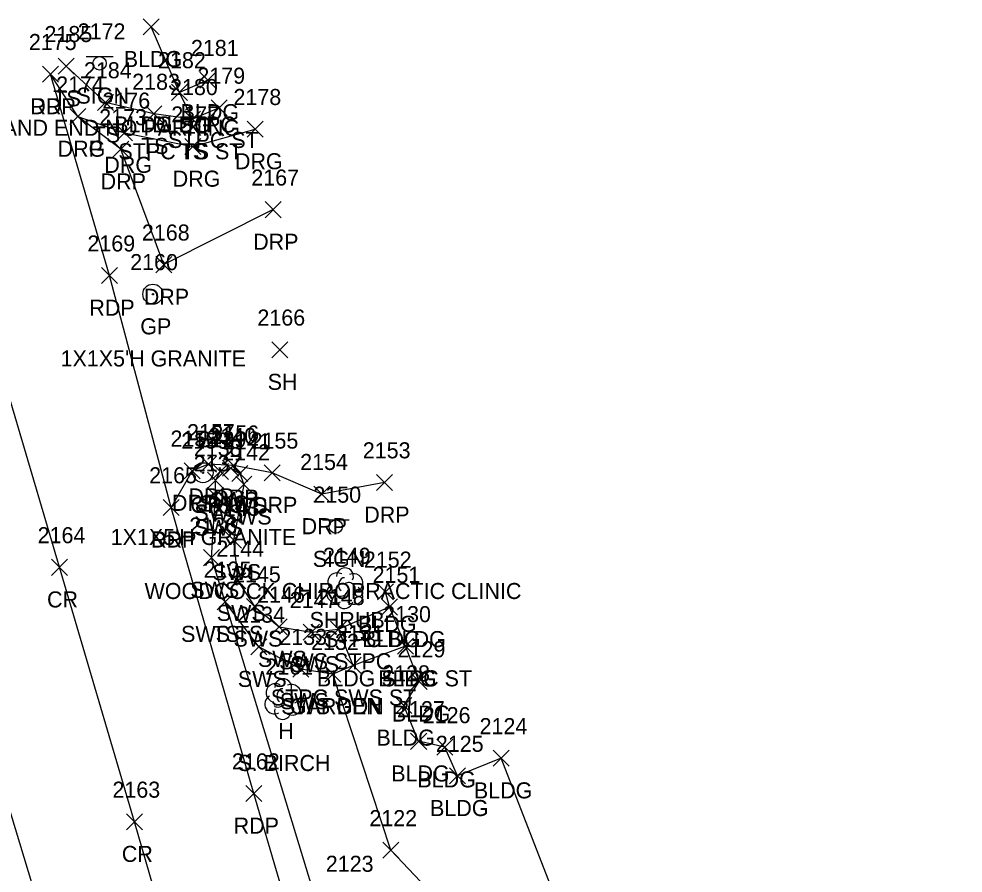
# Model space of a CAD drawing. Extents: x 1620157 to 1620595, y 115111 to 117885.
# Drawn here: x 1620218.6 to 1620336.2, y 115746 to 115852.3 of the extents above; entities that cross this region are included whole.
import ezdxf

# ---------------------------------------------------------------- set-up
doc = ezdxf.new("R2010")
doc.units = 0
for name, color, linetype in [('L_A', 7, 'Continuous'), ('L_C', 7, 'Continuous'), ('L_I', 7, 'Continuous'), ('L_TIC', 7, 'Continuous'), ('LAPB', 7, 'Continuous'), ('LBC', 7, 'Continuous'), ('LBF', 7, 'Continuous'), ('LELB', 7, 'Continuous'), ('LSH', 7, 'Continuous'), ('LTD', 7, 'Continuous'), ('P_A', 7, 'Continuous'), ('P_I', 7, 'Continuous'), ('P_TIC', 7, 'Continuous'), ('PET', 7, 'Continuous'), ('PRC', 7, 'Continuous'), ('R_A', 7, 'Continuous'), ('R_C', 7, 'Continuous'), ('R_I', 7, 'Continuous'), ('R_TIC', 7, 'Continuous'), ('RDG', 7, 'Continuous'), ('RDP', 7, 'Continuous'), ('RGP', 7, 'Continuous'), ('RSW', 7, 'Continuous'), ('S_A', 7, 'Continuous'), ('S_C', 7, 'Continuous'), ('S_I', 7, 'Continuous'), ('SSGN', 7, 'Continuous')]:
    doc.layers.add(name, color=color, linetype=linetype)

msp = doc.modelspace()

# ---------------------------------------------------------------- linework, layer by layer
at = {"layer": 'L_TIC'}
for points in [[(1620234.05, 115850.34), (1620236.05, 115852.34)], [(1620236.05, 115850.34), (1620234.05, 115852.34)], [(1620223.46, 115845.45), (1620225.46, 115847.45)], [(1620225.46, 115845.45), (1620223.46, 115847.45)], [(1620241.14, 115843.72), (1620243.14, 115845.72)], [(1620243.14, 115843.72), (1620241.14, 115845.72)], [(1620237.61, 115842.19), (1620239.61, 115844.19)], [(1620239.61, 115842.19), (1620237.61, 115844.19)], [(1620237.61, 115842.19), (1620239.61, 115844.19)], [(1620239.61, 115842.19), (1620237.61, 115844.19)], [(1620228.39, 115840.94), (1620230.39, 115842.94)], [(1620230.39, 115840.94), (1620228.39, 115842.94)], [(1620234.39, 115839.51), (1620236.39, 115841.51)], [(1620236.39, 115839.51), (1620234.39, 115841.51)], [(1620242.53, 115840.26), (1620244.53, 115842.26)], [(1620244.53, 115840.26), (1620242.53, 115842.26)], [(1620239.2, 115838.85), (1620241.2, 115840.85)], [(1620241.2, 115838.85), (1620239.2, 115840.85)], [(1620239.2, 115838.85), (1620241.2, 115840.85)], [(1620241.2, 115838.85), (1620239.2, 115840.85)], [(1620250.09, 115810.14), (1620252.09, 115812.14)], [(1620252.09, 115810.14), (1620250.09, 115812.14)], [(1620263.25, 115780), (1620265.25, 115782)], [(1620265.25, 115780), (1620263.25, 115782)], [(1620243.29, 115778.75), (1620245.29, 115780.75)], [(1620245.29, 115778.75), (1620243.29, 115780.75)], [(1620263.77, 115778.1), (1620265.77, 115780.1)], [(1620265.77, 115778.1), (1620263.77, 115780.1)], [(1620263.77, 115778.1), (1620265.77, 115780.1)], [(1620265.77, 115778.1), (1620263.77, 115780.1)], [(1620257.41, 115775.34), (1620259.41, 115777.34)], [(1620259.41, 115775.34), (1620257.41, 115777.34)], [(1620265.75, 115773.21), (1620267.75, 115775.21)], [(1620267.75, 115773.21), (1620265.75, 115775.21)], [(1620265.75, 115773.21), (1620267.75, 115775.21)], [(1620267.75, 115773.21), (1620265.75, 115775.21)], [(1620259.23, 115770.83), (1620261.23, 115772.83)], [(1620261.23, 115770.83), (1620259.23, 115772.83)], [(1620256.68, 115769.75), (1620258.68, 115771.75)], [(1620258.68, 115769.75), (1620256.68, 115771.75)], [(1620267.47, 115768.83), (1620269.47, 115770.83)], [(1620269.47, 115768.83), (1620267.47, 115770.83)], [(1620265.54, 115765.83), (1620267.54, 115767.83)], [(1620267.54, 115765.83), (1620265.54, 115767.83)], [(1620267.39, 115761.37), (1620269.39, 115763.37)], [(1620269.39, 115761.37), (1620267.39, 115763.37)], [(1620270.64, 115760.63), (1620272.64, 115762.63)], [(1620272.64, 115760.63), (1620270.64, 115762.63)], [(1620277.68, 115759.26), (1620279.68, 115761.26)], [(1620279.68, 115759.26), (1620277.68, 115761.26)], [(1620272.22, 115757.06), (1620274.22, 115759.06)], [(1620274.22, 115757.06), (1620272.22, 115759.06)], [(1620263.94, 115747.8), (1620265.94, 115749.8)], [(1620265.94, 115747.8), (1620263.94, 115749.8)]]:
    msp.add_lwpolyline(points, dxfattribs=at)
at = {"layer": 'LAPB'}
msp.add_lwpolyline([(1620278.22, 115734.77), (1620264.94, 115748.8), (1620257.68, 115770.75)], dxfattribs=at)
at = {"layer": 'LBC'}
for points in [[(1620242.14, 115844.72), (1620238.61, 115843.19), (1620235.05, 115851.34)], [(1620286.48, 115740.19), (1620278.68, 115760.26), (1620273.22, 115758.06), (1620271.64, 115761.63), (1620268.39, 115762.37), (1620266.54, 115766.83), (1620268.47, 115769.83), (1620266.75, 115774.21), (1620264.77, 115779.1), (1620264.25, 115781)]]:
    msp.add_lwpolyline(points, dxfattribs=at)
at = {"layer": 'LBF'}
for points in [[(1620243.53, 115841.26), (1620240.2, 115839.85), (1620238.61, 115843.19)], [(1620266.75, 115774.21), (1620260.23, 115771.83), (1620258.41, 115776.34), (1620264.77, 115779.1)]]:
    msp.add_lwpolyline(points, dxfattribs=at)
at = {"layer": 'LELB'}
for points in [[(1620240.2, 115839.85), (1620235.39, 115840.51), (1620229.39, 115841.94), (1620224.46, 115846.45)], [(1620266.61, 115701.28), (1620260.83, 115725.5), (1620244.29, 115779.75)]]:
    msp.add_lwpolyline(points, dxfattribs=at)
at = {"layer": 'LSH'}
msp.add_line((1620259.17, 115781.48), (1620259.17, 115781.48), dxfattribs=at)
msp.add_line((1620259.17, 115781.48), (1620259.17, 115781.48), dxfattribs=at)
msp.add_arc((1620259.21, 115782.91), 1.05, 335.5272, 180.9563, dxfattribs=at)
for centre, major_axis, ratio, start_param, end_param in [((1620258.37, 115782.15), (1.21, -0.51), 0.895232, 1.570796, 4.712389), ((1620258.96, 115781.94), (-0.208, -0.792), 0.645439, 3.141593, 6.283185), ((1620260.21, 115782.06), (-1.14, -0.48), 0.949671, 1.570796, 4.712389), ((1620258.08, 115780.77), (0.58, -1.04), 0.959034, 3.141593, 6.283185), ((1620259.67, 115781.31), (-0.5, 0.667), 0.989748, 3.141593, 6.283185), ((1620260.17, 115780.65), (-1.09, 0.79), 0.841452, 1.570796, 4.712389), ((1620259.17, 115779.98), (0.26, 1.06), 0.942809, 1.570796, 4.712389), ((1620258.71, 115780.73), (-0.625, -0.083), 0.423636, 0, 3.141593)]:
    msp.add_ellipse(centre, major_axis=major_axis, ratio=ratio, start_param=start_param, end_param=end_param, dxfattribs=at)
at = {"layer": 'LTD'}
msp.add_line((1620251.46, 115767.67), (1620251.46, 115767.67), dxfattribs=at)
msp.add_line((1620251.46, 115767.67), (1620251.46, 115767.67), dxfattribs=at)
msp.add_arc((1620251.51, 115769.11), 1.05, 335.5272, 180.9563, dxfattribs=at)
for centre, major_axis, ratio, start_param, end_param in [((1620250.67, 115768.34), (1.21, -0.51), 0.895232, 1.570796, 4.712389), ((1620252.51, 115768.26), (-1.14, -0.48), 0.949671, 1.570796, 4.712389), ((1620251.26, 115768.13), (-0.208, -0.792), 0.645439, 3.141593, 6.283185), ((1620251.96, 115767.51), (-0.5, 0.667), 0.989748, 3.141593, 6.283185), ((1620250.38, 115766.97), (0.58, -1.04), 0.959034, 3.141593, 6.283185), ((1620252.46, 115766.84), (-1.09, 0.79), 0.841452, 1.570796, 4.712389), ((1620251.46, 115766.17), (0.26, 1.06), 0.942809, 1.570796, 4.712389), ((1620251.01, 115766.92), (-0.625, -0.083), 0.423636, 0, 3.141593)]:
    msp.add_ellipse(centre, major_axis=major_axis, ratio=ratio, start_param=start_param, end_param=end_param, dxfattribs=at)
at = {"layer": 'P_TIC'}
for points in [[(1620221.52, 115844.46), (1620223.52, 115846.46)], [(1620223.52, 115844.46), (1620221.52, 115846.46)], [(1620228.87, 115819.37), (1620230.87, 115821.37)], [(1620230.87, 115819.37), (1620228.87, 115821.37)], [(1620236.56, 115790.5), (1620238.56, 115792.5)], [(1620238.56, 115790.5), (1620236.56, 115792.5)], [(1620222.66, 115783.04), (1620224.66, 115785.04)], [(1620224.66, 115783.04), (1620222.66, 115785.04)], [(1620246.86, 115754.87), (1620248.86, 115756.87)], [(1620248.86, 115754.87), (1620246.86, 115756.87)], [(1620231.98, 115751.35), (1620233.98, 115753.35)], [(1620233.98, 115751.35), (1620231.98, 115753.35)]]:
    msp.add_lwpolyline(points, dxfattribs=at)
at = {"layer": 'PET'}
for points in [[(1620336.22, 115456.8), (1620332.52, 115469.32), (1620324.59, 115500.95), (1620318.09, 115527.23), (1620313.06, 115541.76), (1620309.74, 115554.43), (1620302.9, 115574.33), (1620297.63, 115590.44), (1620296.31, 115595.42), (1620295.45, 115598.55), (1620285.02, 115631.41), (1620284, 115634.58), (1620271.05, 115676.55), (1620263.94, 115701.46), (1620257.2, 115724.05), (1620247.86, 115755.87), (1620237.56, 115791.5), (1620229.87, 115820.37), (1620222.52, 115845.46)], [(1620320.14, 115439.39), (1620314.87, 115455.06), (1620309.06, 115464.39), (1620304.22, 115479.4), (1620297.09, 115496.09), (1620293.95, 115506.93), (1620292.02, 115512.47), (1620283.67, 115536.02), (1620274.58, 115564.81), (1620268.48, 115584.52), (1620253.11, 115635.23), (1620250.12, 115643.88), (1620242.65, 115668.01), (1620237.66, 115684.19), (1620235.08, 115693.76), (1620231.19, 115707.41), (1620225.41, 115727.43), (1620211.93, 115771.95), (1620203.83, 115799.04), (1620193.37, 115837.22)]]:
    msp.add_lwpolyline(points, dxfattribs=at)
at = {"layer": 'PRC'}
msp.add_lwpolyline([(1620328.08, 115447.46), (1620322.14, 115466.61), (1620311.32, 115499.81), (1620303.78, 115522.91), (1620294.72, 115551.74), (1620279.31, 115600.23), (1620271.12, 115626.45), (1620257.91, 115669.49), (1620247.64, 115703.03), (1620242.45, 115719.65), (1620232.98, 115752.35), (1620223.66, 115784.04), (1620214.14, 115816.15), (1620207.47, 115841.18)], dxfattribs=at)
at = {"layer": 'R_TIC'}
for points in [[(1620221.52, 115844.46), (1620223.52, 115846.46)], [(1620223.52, 115844.46), (1620221.52, 115846.46)], [(1620224.92, 115839.17), (1620226.92, 115841.17)], [(1620226.92, 115839.17), (1620224.92, 115841.17)], [(1620224.92, 115839.17), (1620226.92, 115841.17)], [(1620226.92, 115839.17), (1620224.92, 115841.17)], [(1620230.74, 115837.16), (1620232.74, 115839.16)], [(1620232.74, 115837.16), (1620230.74, 115839.16)], [(1620247.01, 115837.61), (1620249.01, 115839.61)], [(1620249.01, 115837.61), (1620247.01, 115839.61)], [(1620230.28, 115835.1), (1620232.28, 115837.1)], [(1620232.28, 115835.1), (1620230.28, 115837.1)], [(1620239.26, 115835.44), (1620241.26, 115837.44)], [(1620241.26, 115835.44), (1620239.26, 115837.44)], [(1620249.28, 115827.58), (1620251.28, 115829.58)], [(1620251.28, 115827.58), (1620249.28, 115829.58)], [(1620235.65, 115820.73), (1620237.65, 115822.73)], [(1620237.65, 115820.73), (1620235.65, 115822.73)], [(1620241.22, 115795.87), (1620243.22, 115797.87)], [(1620243.22, 115795.87), (1620241.22, 115797.87)], [(1620244.31, 115795.71), (1620246.31, 115797.71)], [(1620246.31, 115795.71), (1620244.31, 115797.71)], [(1620239.16, 115795.07), (1620241.16, 115797.07)], [(1620241.16, 115795.07), (1620239.16, 115797.07)], [(1620242.68, 115794.98), (1620244.68, 115796.98)], [(1620244.68, 115794.98), (1620242.68, 115796.98)], [(1620243.97, 115795.4), (1620245.97, 115797.4)], [(1620245.97, 115795.4), (1620243.97, 115797.4)], [(1620245.12, 115794.73), (1620247.12, 115796.73)], [(1620247.12, 115794.73), (1620245.12, 115796.73)], [(1620249.15, 115794.82), (1620251.15, 115796.82)], [(1620251.15, 115794.82), (1620249.15, 115796.82)], [(1620242.08, 115793.87), (1620244.08, 115795.87)], [(1620244.08, 115793.87), (1620242.08, 115795.87)], [(1620245.61, 115793.37), (1620247.61, 115795.37)], [(1620247.61, 115793.37), (1620245.61, 115795.37)], [(1620263.13, 115793.61), (1620265.13, 115795.61)], [(1620265.13, 115793.61), (1620263.13, 115795.61)], [(1620255.33, 115792.16), (1620257.33, 115794.16)], [(1620257.33, 115792.16), (1620255.33, 115794.16)], [(1620242.06, 115791.98), (1620244.06, 115793.98)], [(1620244.06, 115791.98), (1620242.06, 115793.98)], [(1620236.56, 115790.5), (1620238.56, 115792.5)], [(1620238.56, 115790.5), (1620236.56, 115792.5)], [(1620244.31, 115786.44), (1620246.31, 115788.44)], [(1620246.31, 115786.44), (1620244.31, 115788.44)], [(1620241.57, 115784.24), (1620243.57, 115786.24)], [(1620243.57, 115784.24), (1620241.57, 115786.24)], [(1620244.87, 115781.36), (1620246.87, 115783.36)], [(1620246.87, 115781.36), (1620244.87, 115783.36)], [(1620243.29, 115778.75), (1620245.29, 115780.75)], [(1620245.29, 115778.75), (1620243.29, 115780.75)], [(1620246.95, 115778.16), (1620248.95, 115780.16)], [(1620248.95, 115778.16), (1620246.95, 115780.16)], [(1620250, 115775.64), (1620252, 115777.64)], [(1620252, 115775.64), (1620250, 115777.64)], [(1620254.02, 115774.97), (1620256.02, 115776.97)], [(1620256.02, 115774.97), (1620254.02, 115776.97)], [(1620257.41, 115775.34), (1620259.41, 115777.34)], [(1620259.41, 115775.34), (1620257.41, 115777.34)], [(1620247.49, 115773.14), (1620249.49, 115775.14)], [(1620249.49, 115773.14), (1620247.49, 115775.14)], [(1620252.72, 115770.37), (1620254.72, 115772.37)], [(1620254.72, 115770.37), (1620252.72, 115772.37)], [(1620259.23, 115770.83), (1620261.23, 115772.83)], [(1620261.23, 115770.83), (1620259.23, 115772.83)], [(1620256.68, 115769.75), (1620258.68, 115771.75)], [(1620258.68, 115769.75), (1620256.68, 115771.75)]]:
    msp.add_lwpolyline(points, dxfattribs=at)
at = {"layer": 'RDG'}
msp.add_lwpolyline([(1620225.92, 115840.17), (1620231.74, 115838.16), (1620240.26, 115836.44), (1620248.01, 115838.61)], dxfattribs=at)
at = {"layer": 'RDP'}
for points in [[(1620250.28, 115828.58), (1620236.65, 115821.73), (1620231.28, 115836.1), (1620225.92, 115840.17), (1620222.52, 115845.46)], [(1620264.13, 115794.61), (1620256.33, 115793.16), (1620250.15, 115795.82), (1620245.31, 115796.71), (1620242.22, 115796.87), (1620240.16, 115796.07), (1620237.56, 115791.5)]]:
    msp.add_lwpolyline(points, dxfattribs=at)
at = {"layer": 'RGP'}
for p, q in [((1620235.28, 115818.05), (1620235.28, 115818.05)), ((1620241.52, 115795.82), (1620241.52, 115795.82))]:
    msp.add_line(p, q, dxfattribs=at)
for centre, radius in [((1620235.28, 115818.05), 1.25), ((1620235.28, 115818.05), 0.0833), ((1620241.52, 115795.82), 1.25), ((1620241.52, 115795.82), 0.0833)]:
    msp.add_circle(centre, radius, dxfattribs=at)
at = {"layer": 'RSW'}
msp.add_lwpolyline([(1620260.23, 115771.83), (1620257.68, 115770.75), (1620253.72, 115771.37), (1620248.49, 115774.14), (1620244.29, 115779.75), (1620242.57, 115785.24), (1620243.06, 115792.98), (1620243.08, 115794.87), (1620243.68, 115795.98), (1620244.97, 115796.4), (1620246.12, 115795.73), (1620246.61, 115794.37), (1620245.31, 115787.44), (1620245.87, 115782.36), (1620247.95, 115779.16), (1620251, 115776.64), (1620255.02, 115775.97), (1620258.41, 115776.34)], dxfattribs=at)
at = {"layer": 'SSGN'}
for p, q in [((1620226.98, 115847.64), (1620230.31, 115847.64)), ((1620228.63, 115846.8), (1620228.63, 115846.8)), ((1620256.42, 115789.94), (1620259.75, 115789.94)), ((1620258.06, 115789.11), (1620258.06, 115789.11))]:
    msp.add_line(p, q, dxfattribs=at)
for centre in [(1620228.63, 115846.8), (1620258.06, 115789.11)]:
    msp.add_circle(centre, 0.833, dxfattribs=at)

# ---------------------------------------------------------------- texts
at = {"layer": 'L_A'}
for s, p in [('BLDG', (1620231.65, 115846.34)), ('TS', (1620222.87, 115841.45)), ('BLDG', (1620238.73, 115839.72)), ('BLDG STPC', (1620230.45, 115838.19)), ('BLDG', (1620235.2, 115838.19)), ('TS', (1620227.79, 115836.94)), ('STPC ST', (1620237.17, 115836.26)), ('STPC TS ST', (1620230.98, 115834.85)), ('TS', (1620233.8, 115835.51)), ('TS', (1620238.61, 115834.85)), ('SH', (1620249.58, 115806.14)), ('SHRUB', (1620254.8, 115776.48)), ('BLDG', (1620260.84, 115776)), ('TS', (1620242.7, 115774.75)), ('STPC BLDG', (1620256.61, 115774.1)), ('BLDG', (1620261.36, 115774.1)), ('SWS STPC', (1620251.01, 115771.34)), ('BLDG STPC ST', (1620255.72, 115769.21)), ('BLDG', (1620263.34, 115769.21)), ('STPC SWS ST', (1620249.97, 115766.83)), ('GARDEN', (1620252.35, 115765.75)), ('BLDG', (1620265.06, 115764.83)), ('H', (1620250.9, 115762.67)), ('BLDG', (1620263.13, 115761.83)), ('BLDG', (1620264.98, 115757.37)), ('BLDG', (1620268.23, 115756.63)), ('BLDG', (1620275.27, 115755.26)), ('BLDG', (1620269.81, 115753.06))]:
    msp.add_text(s, height=2, dxfattribs=at).set_placement(p)
at = {"layer": 'L_C'}
msp.add_text('S. BIRCH', height=2, dxfattribs=at).set_placement((1620245.81, 115758.67))
at = {"layer": 'L_I'}
for s, p in [('2185', (1620221.77, 115849.45)), ('2181', (1620240.02, 115847.72)), ('2182', (1620235.92, 115846.19)), ('2182', (1620235.92, 115846.19)), ('2184', (1620226.69, 115844.94)), ('2179', (1620240.82, 115844.26)), ('2183', (1620232.7, 115843.51)), ('2180', (1620237.42, 115842.85)), ('2180', (1620237.42, 115842.85)), ('2166', (1620248.3, 115814.14)), ('2149', (1620256.47, 115784.48)), ('2152', (1620261.56, 115784)), ('2135', (1620241.6, 115782.75)), ('2151', (1620262.65, 115782.1)), ('2151', (1620262.65, 115782.1)), ('2148', (1620255.72, 115779.34)), ('2130', (1620263.97, 115777.21)), ('2130', (1620263.97, 115777.21)), ('2131', (1620258.1, 115774.83)), ('2132', (1620254.99, 115773.75)), ('2129', (1620265.77, 115772.83)), ('2161', (1620249.29, 115770.67)), ('2128', (1620263.85, 115769.83)), ('2127', (1620265.7, 115765.37)), ('2126', (1620268.9, 115764.63)), ('2124', (1620275.98, 115763.26)), ('2125', (1620270.53, 115761.06)), ('2122', (1620262.25, 115751.8)), ('2123', (1620256.82, 115746.12))]:
    msp.add_text(s, height=2, dxfattribs=at).set_placement(p)
at = {"layer": 'P_A'}
for s, p in [('RDP', (1620220.01, 115840.46)), ('RDP', (1620227.36, 115815.37)), ('RDP', (1620235.05, 115786.5)), ('CR', (1620222.09, 115779.04)), ('RDP', (1620245.34, 115750.87)), ('CR', (1620231.41, 115747.35))]:
    msp.add_text(s, height=2, dxfattribs=at).set_placement(p)
at = {"layer": 'P_I'}
for s, p in [('2175', (1620219.83, 115848.46)), ('2169', (1620227.12, 115823.37)), ('2165', (1620234.82, 115794.5)), ('2164', (1620220.92, 115787.04)), ('2162', (1620245.12, 115758.87)), ('2163', (1620230.24, 115755.35))]:
    msp.add_text(s, height=2, dxfattribs=at).set_placement(p)
at = {"layer": 'R_A'}
for s, p in [('DRP', (1620220.01, 115840.46)), ('DRG', (1620223.41, 115835.17)), ('DRP', (1620223.41, 115835.17)), ('DRG', (1620245.5, 115833.61)), ('DRG', (1620229.23, 115833.16)), ('DRP', (1620228.77, 115831.1)), ('DRG', (1620237.75, 115831.44)), ('DRP', (1620247.77, 115823.58)), ('DRP', (1620234.14, 115816.73)), ('GP', (1620233.71, 115813.05)), ('DRP', (1620237.65, 115791.07)), ('DRP', (1620239.71, 115791.87)), ('SWS', (1620241.05, 115790.98)), ('SWS', (1620242.34, 115791.4)), ('DRP', (1620242.8, 115791.71)), ('GP', (1620239.95, 115790.82)), ('SWS', (1620240.45, 115789.87)), ('SWS', (1620243.49, 115790.73)), ('DRP', (1620247.63, 115790.82)), ('SWS', (1620243.98, 115789.37)), ('DRP', (1620261.61, 115789.61)), ('SWS', (1620240.43, 115787.98)), ('DRP', (1620253.81, 115788.16)), ('DRP', (1620235.05, 115786.5)), ('SWS', (1620242.68, 115782.44)), ('SWS', (1620239.94, 115780.24)), ('SWS', (1620243.24, 115777.36)), ('SWS TS', (1620238.79, 115774.75)), ('SWS', (1620245.32, 115774.16)), ('SWS', (1620248.37, 115771.64)), ('SWS STPC', (1620251.01, 115771.34)), ('SWS', (1620252.39, 115770.97)), ('SWS', (1620245.86, 115769.14)), ('STPC SWS ST', (1620249.97, 115766.83)), ('SWS', (1620251.09, 115766.37)), ('SWS GDN', (1620251.26, 115765.75))]:
    msp.add_text(s, height=2, dxfattribs=at).set_placement(p)
at = {"layer": 'R_C'}
for p in [(1620223.78, 115809.05), (1620230.02, 115786.82)]:
    msp.add_text("1X1X5'H GRANITE", height=2, dxfattribs=at).set_placement(p)
at = {"layer": 'R_I'}
for s, p in [('2175', (1620219.83, 115848.46)), ('2174', (1620223.23, 115843.17)), ('2174', (1620223.23, 115843.17)), ('2178', (1620245.32, 115841.61)), ('2176', (1620228.99, 115841.16)), ('2177', (1620237.57, 115839.44)), ('2173', (1620228.59, 115839.1)), ('2167', (1620247.54, 115831.58)), ('2168', (1620233.91, 115824.73)), ('2160', (1620232.45, 115821.05)), ('2157', (1620239.53, 115799.87)), ('2140', (1620242.19, 115799.4)), ('2156', (1620242.56, 115799.71)), ('2158', (1620237.47, 115799.07)), ('2159', (1620238.82, 115798.82)), ('2139', (1620240.98, 115798.98)), ('2141', (1620244, 115798.73)), ('2155', (1620247.45, 115798.82)), ('2138', (1620240.39, 115797.87)), ('2142', (1620243.92, 115797.37)), ('2153', (1620261.43, 115797.61)), ('2137', (1620240.37, 115795.98)), ('2154', (1620253.63, 115796.16)), ('2165', (1620234.82, 115794.5)), ('2143', (1620242.62, 115790.44)), ('2136', (1620239.82, 115788.24)), ('2144', (1620243.18, 115785.36)), ('2135', (1620241.6, 115782.75)), ('2145', (1620245.26, 115782.16)), ('2146', (1620248.26, 115779.64)), ('2148', (1620255.72, 115779.34)), ('2147', (1620252.32, 115778.97)), ('2134', (1620245.79, 115777.14)), ('2131', (1620258.1, 115774.83)), ('2133', (1620251.03, 115774.37)), ('2132', (1620254.99, 115773.75))]:
    msp.add_text(s, height=2, dxfattribs=at).set_placement(p)
at = {"layer": 'S_A'}
for p in [(1620225.76, 115841.78), (1620255.2, 115784.09)]:
    msp.add_text('SIGN', height=2, dxfattribs=at).set_placement(p)
at = {"layer": 'S_C'}
for s, p in [('BEGIN AND END NO PARKING', (1620207.5, 115837.78)), ('WOODCOCK CHIROPRACTIC CLINIC', (1620234.24, 115780.09))]:
    msp.add_text(s, height=2, dxfattribs=at).set_placement(p)
at = {"layer": 'S_I'}
for s, p in [('2172', (1620225.91, 115849.78)), ('2150', (1620255.27, 115792.09))]:
    msp.add_text(s, height=2, dxfattribs=at).set_placement(p)

doc.saveas('drawing.dxf')
